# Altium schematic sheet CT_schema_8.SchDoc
size 277 x 170 mm
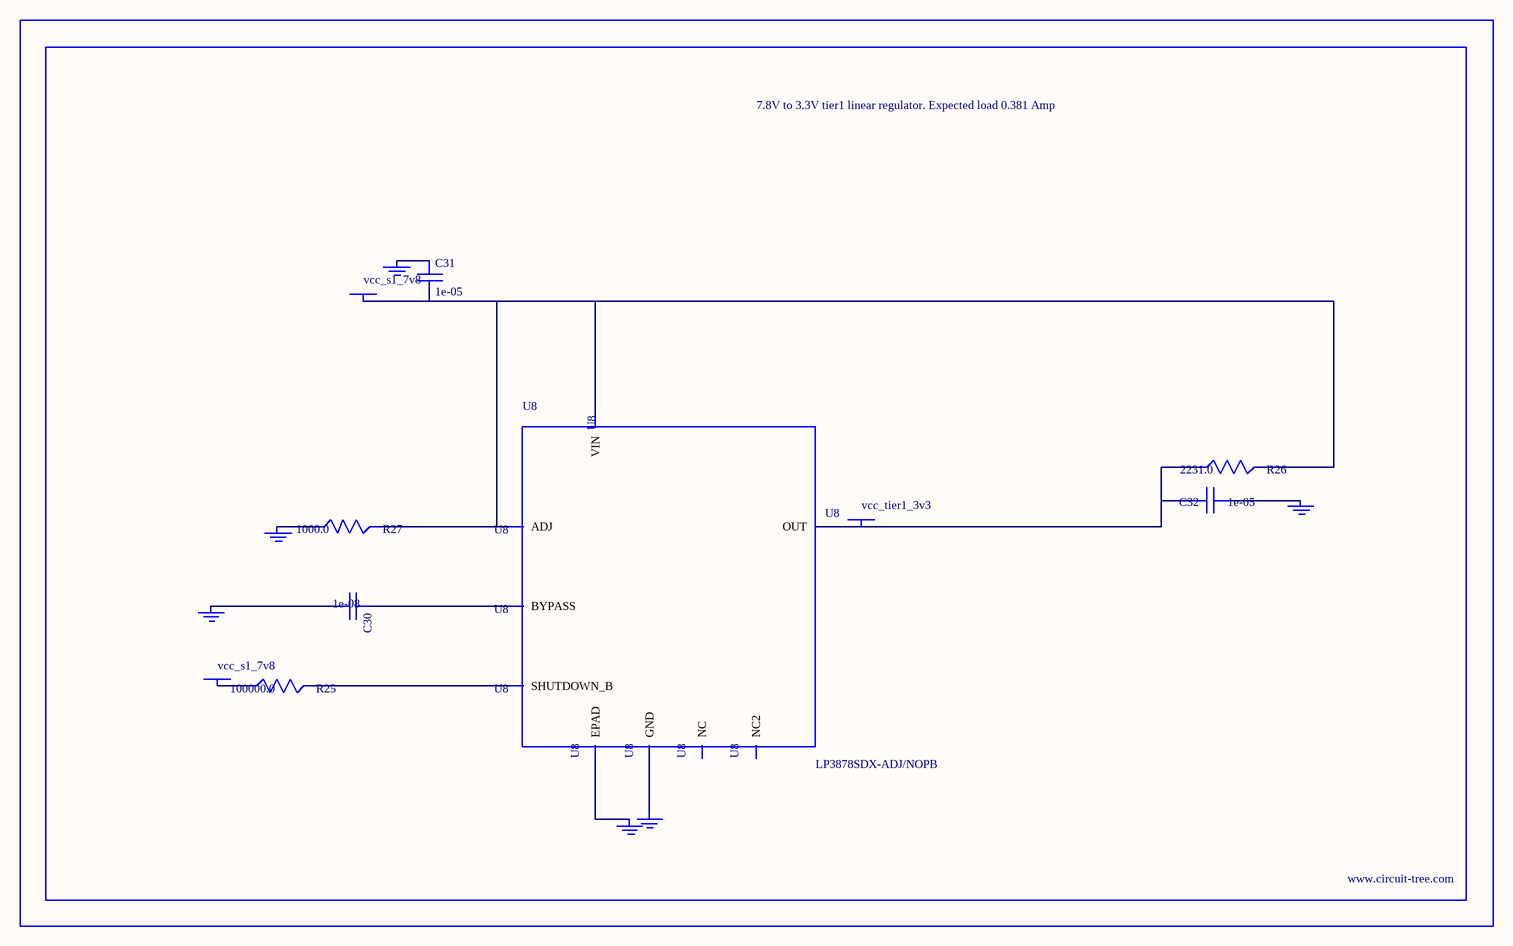
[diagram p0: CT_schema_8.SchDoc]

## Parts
BORDER7  (no value)
C30  1e-08  [C0402]
C31  1e-05  [C1206]
C32  1e-05  [C1210]
GND_INSTANCE_7_0  (no value)
GND_INSTANCE_7_1  (no value)
GND_INSTANCE_7_2  (no value)
GND_INSTANCE_7_3  (no value)
GND_INSTANCE_7_4  (no value)
GND_INSTANCE_7_5  (no value)
POWER_INSTANCE_7_0  vcc_s1_7v8
POWER_INSTANCE_7_1  vcc_s1_7v8
POWER_INSTANCE_7_2  vcc_tier1_3v3
R25  100000.0  [R0603]
R26  2231.0  [R0603]
R27  1000.0  [R0603]
U8  LP3878SDX-ADJ/NOPB  [WSON-8]

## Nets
NetC30_1: C30.1 U8.1(BYPASS)
NetC30_2: C30.2 GND_INSTANCE_7_0.0(GND)
NetC31_1: C31.1 GND_INSTANCE_7_1.0(GND)
NetC31_2: C31.2 POWER_INSTANCE_7_0.0(PWR) R26.2 R27.2 U8.4(VIN) U8.6(ADJ)
NetC32_1: C32.1 GND_INSTANCE_7_2.0(GND)
NetC32_2: C32.2 POWER_INSTANCE_7_2.0(PWR) R26.1 U8.5(OUT)
NetGND_INSTANCE_7_3_0: GND_INSTANCE_7_3.0(GND) R27.1
NetGND_INSTANCE_7_4_0: GND_INSTANCE_7_4.0(GND) U8.PAD(EPAD)
NetGND_INSTANCE_7_5_0: GND_INSTANCE_7_5.0(GND) U8.3(GND)
NetPOWER_INSTANCE_7_1_0: POWER_INSTANCE_7_1.0(PWR) R25.1
NetR25_2: R25.2 U8.8(SHUTDOWN_B)

Not connected (* = marked no-connect by the designer): U8 2(NC) 7(NC2)

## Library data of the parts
BORDER7 = BORDER_PAGE7
C30 = C0402C103K3RAC
C31 = C1206C106K3RACTU
C32 = GRM32DR61E106MA12L
GND_INSTANCE_7_0-GND_INSTANCE_7_5 = GND
POWER_INSTANCE_7_0-POWER_INSTANCE_7_2 = PWR
R25 = RC0603JR-07100KL
R26 = R26
R27 = RC0603JR-071KL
